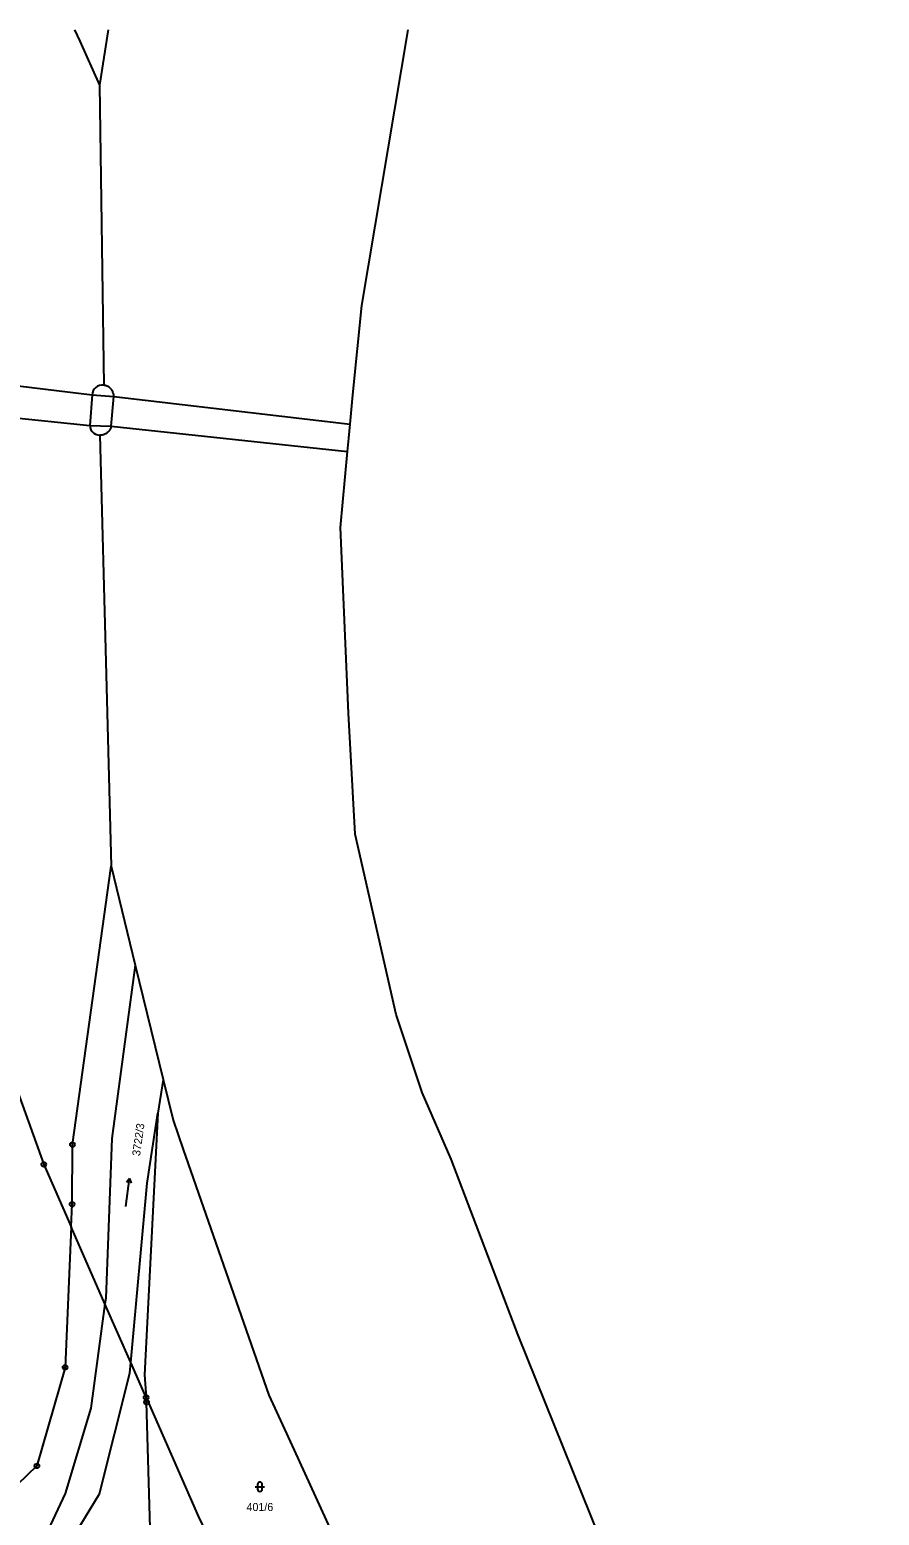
# Model space of a CAD drawing. Extents: x -747779 to -747197, y -965543 to -964919.
# Drawn here: x -747496.8 to -747316.2, y -965237.8 to -964922.2 of the extents above; entities that cross this region are included whole.
import ezdxf

# ---------------------------------------------------------------- set-up
doc = ezdxf.new("R2010")
doc.units = 0
for name, color, linetype in [('Hranice parcel', 7, 'Continuous'), ('Parcelní čísla', 7, 'Continuous'), ('Vnitřní kresba', 7, 'Continuous'), ('Značky bodu BP', 7, 'Continuous'), ('Značky kultur', 7, 'Continuous')]:
    doc.layers.add(name, color=color, linetype=linetype)

msp = doc.modelspace()

# ---------------------------------------------------------------- linework, layer by layer
at = {"layer": 'Hranice parcel'}
msp.add_line((-747483.5, -964999.8), (-747483.98, -965006.3), dxfattribs=at)
for points in [[(-747487.23, -964922.25), (-747486.12, -964924.71), (-747481.93, -964934.01), (-747481.03, -964997.78)], [(-747426.15, -964980.82), (-747416.36, -964922.25)], [(-747430.69, -965028.01), (-747429.22, -965011.83), (-747428.96, -965009.03), (-747428.68, -965006), (-747428.12, -964999.83), (-747426.15, -964980.82)], [(-747481.03, -964997.78), (-747481.49, -964997.75), (-747481.94, -964997.82), (-747482.37, -964997.99), (-747482.7, -964998.21), (-747483.03, -964998.53), (-747483.28, -964998.91), (-747483.44, -964999.34), (-747483.5, -964999.8)], [(-747528.26, -965001.42), (-747527.97, -965001.44), (-747524.98, -965001.63), (-747523.47, -965001.72), (-747523.04, -965020.06), (-747522.04, -965049.05), (-747520.57, -965062.57), (-747513.95, -965097.88), (-747505.52, -965130.78), (-747493.77, -965163.26), (-747487.95, -965176.49)], [(-747483.98, -965006.3), (-747483.91, -965006.76), (-747483.74, -965007.2), (-747483.49, -965007.59), (-747483.16, -965007.91), (-747482.76, -965008.16), (-747482.32, -965008.32), (-747481.86, -965008.38)], [(-747481.86, -965008.38), (-747480.52, -965059.21), (-747479.45, -965099.91)], [(-747418.91, -965131.39), (-747427.62, -965093.15), (-747429.01, -965067.44), (-747430.69, -965028.01)], [(-747487.95, -965176.49), (-747487.75, -965171.72), (-747487.7, -965159.04), (-747479.45, -965099.91)], [(-747479.45, -965099.91), (-747474.33, -965120.92), (-747468.41, -965145.2)], [(-747407.19, -965162.14), (-747413.38, -965147.96), (-747418.91, -965131.39)], [(-747468.41, -965145.2), (-747469.52, -965152.39), (-747472.35, -965207.99), (-747472.02, -965212.77)], [(-747468.41, -965145.2), (-747466.29, -965153.89), (-747464.12, -965160.1), (-747445.94, -965212.26), (-747440.57, -965223.99), (-747422.43, -965263.63), (-747397.43, -965314.99)], [(-747316.19, -965359.38), (-747331.6, -965329.38), (-747371.79, -965252.1), (-747392.97, -965199.55), (-747407.19, -965162.14)], [(-747487.95, -965176.49), (-747489.26, -965206.38), (-747495.23, -965227.3), (-747499.46, -965231.34), (-747501.73, -965233.5), (-747502.29, -965234.04)], [(-747472.02, -965212.77), (-747475.27, -965205.36), (-747480.77, -965192.85), (-747487.95, -965176.49)], [(-747490.69, -965271.24), (-747489.44, -965269.91), (-747487.1, -965267.42), (-747479.18, -965259.01), (-747471.1, -965242.94), (-747471.94, -965213.78), (-747472.02, -965212.77)], [(-747472.02, -965212.77), (-747460.89, -965238.09), (-747438.98, -965282.25)]]:
    msp.add_lwpolyline(points, dxfattribs=at)
at = {"layer": 'Vnitřní kresba'}
for p, q in [((-747480.08, -964922.25), (-747481.93, -964934.01)), ((-747516.92, -964995.72), (-747483.5, -964999.8)), ((-747483.5, -964999.8), (-747478.9, -965000.15)), ((-747479.45, -965006.42), (-747478.9, -965000.15)), ((-747478.9, -965000.15), (-747428.68, -965006)), ((-747517.7, -965002.84), (-747483.98, -965006.3)), ((-747483.98, -965006.3), (-747479.45, -965006.42)), ((-747479.45, -965006.42), (-747429.22, -965011.83)), ((-747474.33, -965120.92), (-747476.26, -965135.1)), ((-747476.26, -965135.1), (-747479.34, -965157.78)), ((-747471.82, -965167.28), (-747469.52, -965152.39)), ((-747479.34, -965157.78), (-747480.61, -965191.69)), ((-747475.27, -965205.36), (-747471.82, -965167.28)), ((-747480.77, -965192.85), (-747483.81, -965215.02)), ((-747480.61, -965191.69), (-747480.77, -965192.85)), ((-747475.48, -965207.62), (-747475.27, -965205.36)), ((-747481.94, -965233.25), (-747475.48, -965207.62)), ((-747483.81, -965215.02), (-747489.21, -965233.16)), ((-747489.21, -965233.16), (-747494.5, -965244.38)), ((-747493.76, -965252.69), (-747481.94, -965233.25))]:
    msp.add_line(p, q, dxfattribs=at)
for points in [[(-747478.9, -965000.15), (-747478.9, -965000.02), (-747478.91, -964999.88), (-747478.92, -964999.74), (-747478.95, -964999.61), (-747478.98, -964999.48), (-747479.02, -964999.35), (-747479.07, -964999.22), (-747479.12, -964999.1), (-747479.18, -964998.98), (-747479.25, -964998.86), (-747479.32, -964998.75), (-747479.4, -964998.64), (-747479.49, -964998.54), (-747479.58, -964998.44), (-747479.68, -964998.35), (-747479.79, -964998.26), (-747479.9, -964998.18), (-747480.01, -964998.11), (-747480.13, -964998.04), (-747480.25, -964997.98), (-747480.37, -964997.93), (-747480.5, -964997.88), (-747480.63, -964997.85), (-747480.76, -964997.82), (-747480.9, -964997.79), (-747481.03, -964997.78)], [(-747479.45, -965006.42), (-747479.48, -965006.55), (-747479.51, -965006.68), (-747479.55, -965006.81), (-747479.6, -965006.94), (-747479.66, -965007.06), (-747479.72, -965007.18), (-747479.79, -965007.3), (-747479.87, -965007.41), (-747479.95, -965007.52), (-747480.04, -965007.62), (-747480.13, -965007.72), (-747480.23, -965007.81), (-747480.34, -965007.9), (-747480.45, -965007.98), (-747480.56, -965008.05), (-747480.68, -965008.11), (-747480.8, -965008.17), (-747480.93, -965008.23), (-747481.06, -965008.27), (-747481.19, -965008.31), (-747481.32, -965008.34), (-747481.45, -965008.36), (-747481.59, -965008.38), (-747481.72, -965008.38), (-747481.86, -965008.38)]]:
    msp.add_lwpolyline(points, dxfattribs=at)
at = {"layer": 'Značky bodu BP'}
for centre, radius in [((-747487.7, -965159.04), 0.5), ((-747487.7, -965159.04), 0.0303), ((-747493.77, -965163.26), 0.5), ((-747493.77, -965163.26), 0.0303), ((-747487.75, -965171.72), 0.5), ((-747487.75, -965171.72), 0.0303), ((-747489.26, -965206.38), 0.5), ((-747489.26, -965206.38), 0.0303), ((-747472.02, -965212.77), 0.5), ((-747472.02, -965212.77), 0.0303), ((-747471.94, -965213.78), 0.5), ((-747471.94, -965213.78), 0.0303), ((-747495.23, -965227.3), 0.5), ((-747495.23, -965227.3), 0.0303)]:
    msp.add_circle(centre, radius, dxfattribs=at)
at = {"layer": 'Značky kultur'}
for p, q in [((-747476.31, -965172.18), (-747475.57, -965166.23)), ((-747475.57, -965166.23), (-747476.19, -965167.14)), ((-747475.57, -965166.23), (-747475.2, -965167.26)), ((-747448.84, -965231.73), (-747446.84, -965231.73)), ((-747448.34, -965231.23), (-747448.34, -965232.23)), ((-747447.34, -965232.23), (-747447.34, -965231.23))]:
    msp.add_line(p, q, dxfattribs=at)
for centre, start, end in [((-747447.84, -965231.23), 0, 180), ((-747447.84, -965232.23), 180, 359.9879)]:
    msp.add_arc(centre, 0.5, start, end, dxfattribs=at)

# ---------------------------------------------------------------- texts
at = {"layer": 'Parcelní čísla'}
msp.add_text('3722/3', height=1.7, rotation=82, dxfattribs=at).set_placement((-747473.33, -965161.56))
msp.add_text('401/6', height=1.7, dxfattribs=at).set_placement((-747450.69, -965236.88))

doc.saveas('drawing.dxf')
